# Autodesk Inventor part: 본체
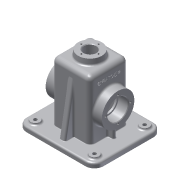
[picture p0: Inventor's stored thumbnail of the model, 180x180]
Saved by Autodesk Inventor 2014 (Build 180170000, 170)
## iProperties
Created: 2016-06
Part Number: 본체
Material: 알루미늄 6061
Document SubType Name: Modeling
Designer: user
Mass: 806.272 g
Surface Area: 909.625 cm^2
Volume: 297.517 cm^3
Density: 2.71 g/cm^3
Appearance: 알루미늄 - 평지
Author: user
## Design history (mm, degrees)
sketch "스케치1"
  geometry: L1 (-50, -52.5)-(50, -52.5); L2 (60, -42.5)-(60, 42.5); L3 (50, 52.5)-(-50, 52.5); L4 (-60, 42.5)-(-60, -42.5); L5 (-60, -52.5)-(60, 52.5); L6 (60, -52.5)-(-60, 52.5); A1 r 10 centre (-50, 42.5) between (-50, 52.5) and (-60, 42.5); A2 r 10 centre (50, 42.5) between (60, 42.5) and (50, 52.5); A3 r 10 centre (50, -42.5) between (50, -52.5) and (60, -42.5); A4 r 10 centre (-50, -42.5) between (-60, -42.5) and (-50, -52.5); 1 further point
  constraints: 12 end point, 8 point on circle, 8 point on line, 8 tangent, 4 centre point, 3 equal radius, 2 midpoint, 2 parallel, 1 horizontal, 1 perpendicular
  dimensions: "d0" = 120 distance of L6.end L5.end; "d1" = 105 distance of L5.end L6.start; "d2" = 10 radius of A1
extrude "돌출1" new body sketch "스케치1" distance "d3" = 2; taper "d4" = 0 deg
sketch "스케치2"
  geometry: L1 (-60, 42.5)-(-60, -42.5) reference; L2 (50, 52.5)-(-50, 52.5) reference; L3 (-60, 42.5)-(-60, -42.5) reference; L4 (-50, -52.5)-(50, -52.5) reference; L5 (60, -42.5)-(60, 42.5) reference; L6 (-50, 57.5)-(50, 57.5); L7 (65, 42.5)-(65, -42.5); L8 (50, -57.5)-(-50, -57.5); L9 (-65, -42.5)-(-65, 42.5); A1 r 10 centre (-50, 42.5) between (-50, 52.5) and (-60, 42.5) reference; A2 r 10 centre (-50, -42.5) between (-60, -42.5) and (-50, -52.5) reference; A3 r 10 centre (50, -42.5) between (50, -52.5) and (60, -42.5) reference; A4 r 10 centre (50, 42.5) between (60, 42.5) and (50, 52.5) reference; A5 r 15 centre (50, 42.5) between (65, 42.5) and (50, 57.5); A6 r 15 centre (50, -42.5) between (50, -57.5) and (65, -42.5); A7 r 15 centre (-50, -42.5) between (-65, -42.5) and (-50, -57.5); A8 r 15 centre (-50, 42.5) between (-50, 57.5) and (-65, 42.5); 1 further point
  constraints: 8 end point, 8 point on circle, 4 centre point, 7 other
  dimensions: "d5" = 5 distance between parallel lines of L1 L9
extrude "돌출2" join sketch "스케치2" distance "d6" = 8; taper "d7" = 0 deg
sketch "스케치3"
  geometry: C1 r 7.5 at (-50, -42.5); C2 r 7.5 at (-50, 42.5); C3 r 7.5 at (50, 42.5); C4 r 7.5 at (50, -42.5); A1 r 15 centre (-50, 42.5) between (-50, 57.5) and (-65, 42.5) reference; A2 r 15 centre (-50, -42.5) between (-65, -42.5) and (-50, -57.5) reference; A3 r 15 centre (50, -42.5) between (50, -57.5) and (65, -42.5) reference; A4 r 15 centre (50, 42.5) between (65, 42.5) and (50, 57.5) reference; 1 further point
  constraints: 4 centre point, 4 coincident
  dimensions: "d8" = 15 diameter of C1; "d9" = 15 diameter of C2; "d10" = 15 diameter of C3; "d11" = 15 diameter of C4
extrude "돌출3" join sketch "스케치3" distance "d12" = 3; taper "d13" = 0 deg
fillet "모깎기1" dims "d14" = 3
sketch "스케치4"
  geometry: C1 r 7.5 at (0, 0) reference; C2 r 7.5 at (100, 0) reference; C3 r 7.5 at (100, -85) reference; C4 r 7.5 at (0, -85) reference; 5 further points
  constraints: 4 coincident
hole "구멍1" sketch "스케치4" at (0, 0), (100, 0), (100, -85), (0, -85) diameter "d15" = 6; stored, may be unused: countersink angle "d19" = 90 deg, drill point angle "d21" = 118 deg; dims "d16" = 6, "d17" = 4, "d18" = 2, "d20" = 8
sketch "스케치5"
  geometry: L1 (-32.5, -32.5)-(32.5, -32.5); L2 (32.5, -32.5)-(32.5, 32.5); L3 (32.5, 32.5)-(-32.5, 32.5); L4 (-32.5, 32.5)-(-32.5, -32.5); L5 (-32.5, -32.5)-(32.5, 32.5); L6 (32.5, -32.5)-(-32.5, 32.5); 1 further point
  constraints: 12 end point, 2 midpoint, 2 parallel, 1 horizontal, 1 perpendicular
  dimensions: "d22" = 65 distance of L3.end L2.end; "d23" = 65 distance of L2.end L1.end
extrude "돌출4" join sketch "스케치5" distance "d24" = 100; taper "d25" = 0 deg
fillet "모깎기2" dims "d26" = 8
fillet "모깎기3" dims "d27" = 8
node "작업 평면1"
sketch "스케치7"
  geometry: C1 r 20 at (0, 0); 1 further point
  constraints: 1 centre point, 1 coincident
  dimensions: "d29" = 40 diameter of C1
extrude "돌출5" join sketch "스케치7" stored distance "d30" = 100; taper "d31" = 5 deg
fillet "모깎기4" dims "d32" = 3
sketch "스케치8"
  geometry: L1 (-27.5, 27.5)-(27.5, 27.5); L2 (27.5, 27.5)-(27.5, -27.5); L3 (27.5, -27.5)-(-27.5, -27.5); L4 (-27.5, -27.5)-(-27.5, 27.5); L5 (-27.5, 27.5)-(27.5, -27.5); L6 (27.5, 27.5)-(-27.5, -27.5); 1 further point
  constraints: 12 end point, 2 midpoint, 2 parallel, 1 horizontal, 1 perpendicular
  dimensions: "d33" = 55 distance of L2.end L3.end; "d34" = 55 distance of L1.end L2.end
extrude "돌출6" cut sketch "스케치8" distance "d35" = 105; taper "d36" = 0 deg
fillet "모깎기5" dims "d37" = 3
fillet "모깎기6" dims "d38" = 3
sketch "스케치9"
  geometry: C1 r 20 at (0, 0) reference; 1 further point
  constraints: 1 coincident
hole "구멍2" sketch "스케치9" at (0, 0) diameter "d39" = 21; stored, may be unused: countersink angle "d43" = 90 deg, drill point angle "d45" = 118 deg; dims "d40" = 6, "d41" = 4, "d42" = 2, "d44" = 8
chamfer "모따기1" distance "d46" = 1; stored, may be unused: second distance "d47" = 2, angle "d48" = 45 deg
sketch "스케치10"
  geometry: C1 r 20 at (0, 0) reference; C2 r 11.5 at (0, 0) reference; A1 r 14.5 centre (0, 0) between (0, 14.5) and (14.5, 0); 2 further points
  constraints: 4 point on circle, 2 horizontal alignment, 2 vertical alignment, 1 centre point, 1 coincident
  dimensions: "d49" = 29 diameter of A1
hole "구멍3" sketch "스케치10" at (0, 14.5), (0, -14.5), (-14.5, 0), (14.5, 0) diameter "d50" = 2.459; stored, may be unused: countersink angle "d54" = 90 deg, drill point angle "d56" = 118 deg; dims "d51" = 7, "d52" = 4, "d53" = 2, "d55" = 9
sketch "스케치11"
  geometry: C1 r 27.5 at (-45, 24.5); 1 further point
  constraints: 1 centre point, 1 horizontal alignment
  dimensions: "d57" = 55 diameter of C1; "d58" = 55 distance of C1.centre point (10, 24.5)
extrude "돌출7" join sketch "스케치11" distance "d59" = 15; taper "d60" = 0 deg
sketch "스케치12"
  geometry: C1 r 27.5 at (0, 0) reference; 2 further points
  constraints: 1 coincident
hole "구멍4" sketch "스케치12" at (0, 0) diameter "d61" = 30; stored, may be unused: countersink angle "d65" = 90 deg, drill point angle "d67" = 0 deg; dims "d62" = 7, "d63" = 35, "d64" = 17, "d66" = 20
chamfer "모따기2" distance "d68" = 1; stored, may be unused: second distance "d69" = 2, angle "d70" = 45 deg
sketch "스케치13"
  geometry: C1 r 27.5 at (0, 0) reference; C2 r 18.5 at (0, 0) reference; A1 r 21 centre (0, 0) between (0, 21) and (21, 0); 3 further points
  constraints: 4 point on circle, 2 horizontal alignment, 2 vertical alignment, 1 centre point, 1 coincident
  dimensions: "d71" = 42 diameter of A1
hole "구멍5" sketch "스케치13" at (0, 21), (0, -21), (-21, 0), (21, 0) diameter "d72" = 3.242; stored, may be unused: countersink angle "d76" = 90 deg, drill point angle "d78" = 118 deg; dims "d73" = 8, "d74" = 35, "d75" = 17, "d77" = 10
sketch "스케치14"
  geometry: L1 (47.5, 27.5)-(32.5, 27.5) reference; L2 (-50, 10)-(50, 10) reference; L3 (42.5, 27.5)-(42.5, 10); L4 (27.5, 0)-(27.5, 102) reference; 1 further point
  constraints: 2 end point, 2 point on line, 1 vertical
  dimensions: "d79" = 15 distance between parallel lines of L3 L4
feature "리브1" sketch "스케치14" dims "d80" = 1, "d81" = 6, "d82" = 0, "d83" = 0, "d84" = 1, "d85" = 1
fillet "모깎기7" dims "d86" = 3
fillet "모깎기8" dims "d87" = 3
sketch "스케치15"
  geometry: L1 (0, -8)-(92, -8) reference; L2 (-18, 4.5)-(-18, 44.5) reference; A1 r 30.5 centre (47, 24.5) between (28.834, 49) and (28.834, 0) reference; 2 further points
  constraints: 1 horizontal alignment, 1 other
  dimensions: "d88" = 32.5 distance from line of point (8, 24.5) L1 (derived); "d89" = 26 distance from line of point (8, 24.5) L2
feature "엠보싱1" sketch "스케치15" dims "d90" = 0.5, "d91" = 0
sketch "스케치16"
  geometry: L1 (-32.5, 10)-(-32.5, 102) reference; L2 (-32, 10)-(-53, 10) reference; L3 (-57.5, 2)-(-57.5, 7) reference; L4 (-47.5, 10)-(-32.5, 95.069); 1 further point
  constraints: 2 end point, 2 point on line
  dimensions: "d92" = 10 deg angle of L4 L3; "d93" = 10 horizontal distance of L3.end L4.start
feature "리브2" sketch "스케치16" dims "d94" = 1, "d95" = 10, "d96" = 0, "d97" = 0, "d98" = 1, "d99" = 1
fillet "모깎기9" dims "d100" = 3
fillet "모깎기10" dims "d101" = 3
fillet "모깎기11" dims "d102" = 1
fillet "모깎기12" dims "d103" = 0.3
node "솔리드1"
mirror "대칭1"
mirror "대칭2"
mirror "대칭3"
node "투영된 루프1"
node "투영된 루프2"
node "투영된 루프3"
node "투영된 루프4"
